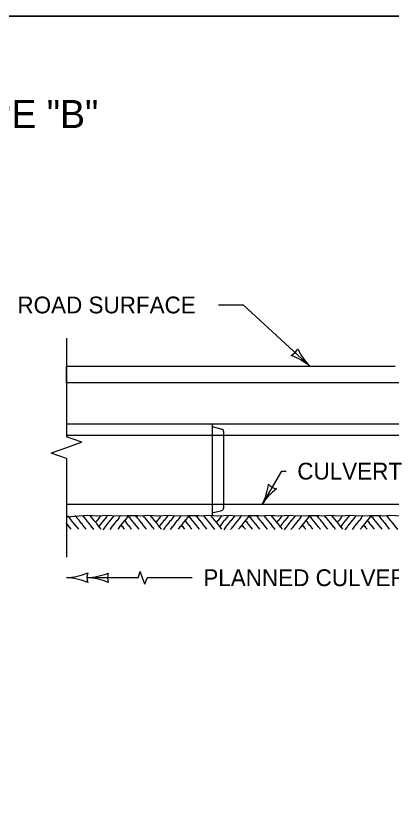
# Model space of a CAD drawing. Extents: x 49991.4 to 50021, y 49987.6 to 50011.4.
# Drawn here: x 50012.469 to 50013.812, y 49996.12 to 49998.999 of the extents above; entities that cross this region are included whole.
import ezdxf

# ---------------------------------------------------------------- set-up
doc = ezdxf.new("R2010")
doc.units = 0
for name, color, linetype in [('Level 1', 7, 'Continuous'), ('Level 2', 7, 'Continuous'), ('Level 3', 7, 'Continuous'), ('Level 4', 7, 'Continuous'), ('Level 6', 7, 'Continuous')]:
    doc.layers.add(name, color=color, linetype=linetype)

msp = doc.modelspace()

# ---------------------------------------------------------------- linework, layer by layer
at = {"layer": 'Level 1'}
for p, q in [((50012.6491, 49997.6892), (50012.6493, 49997.7486)), ((50012.6493, 49997.7486), (50013.8245, 49997.7486)), ((50014.1009, 49997.6892), (50012.6491, 49997.6892)), ((50012.6493, 49997.5423), (50014.7997, 49997.5423)), ((50013.1697, 49997.5423), (50013.1697, 49997.2136))]:
    msp.add_line(p, q, dxfattribs=at)
msp.add_lwpolyline([(49999.3835, 49998.9992), (50016.7501, 49998.9992), (50016.7501, 49987.7988), (49999.3835, 49987.7988)], close=True, dxfattribs=at)
for points in [[(50012.6482, 49997.21), (50012.7245, 49997.2154), (50012.7439, 49997.2142), (50012.7585, 49997.2135)], [(50012.6931, 49997.1653), (50012.6883, 49997.1716), (50012.6867, 49997.1713), (50012.6871, 49997.1727), (50012.6794, 49997.1819), (50012.6799, 49997.1839), (50012.6781, 49997.1841), (50012.6704, 49997.1937), (50012.6687, 49997.1941), (50012.6685, 49997.1959), (50012.6609, 49997.2051), (50012.6613, 49997.207), (50012.6595, 49997.207), (50012.6542, 49997.2135)], [(50012.7195, 49997.1659), (50012.7139, 49997.1731), (50012.7124, 49997.1728), (50012.7127, 49997.1741), (50012.7051, 49997.1835), (50012.7057, 49997.1854), (50012.7037, 49997.1855), (50012.6961, 49997.1953), (50012.6944, 49997.1956), (50012.6943, 49997.1974), (50012.6867, 49997.2065), (50012.6869, 49997.2085), (50012.6849, 49997.2085), (50012.6799, 49997.2149)], [(50012.7473, 49997.1651), (50012.7418, 49997.1725), (50012.7403, 49997.1721), (50012.7405, 49997.1734), (50012.7333, 49997.183), (50012.7335, 49997.1847), (50012.7317, 49997.1849), (50012.7239, 49997.1945), (50012.7223, 49997.195), (50012.7221, 49997.1967), (50012.7147, 49997.2059), (50012.7148, 49997.2076), (50012.7129, 49997.2076), (50012.7079, 49997.2145)], [(50012.7574, 49997.1855), (50012.7502, 49997.1945), (50012.7485, 49997.1951), (50012.7484, 49997.1968), (50012.7407, 49997.2059), (50012.7411, 49997.2079), (50012.7393, 49997.2079), (50012.7337, 49997.2148)], [(50012.7559, 49997.2135), (50012.8029, 49997.2154), (50012.8207, 49997.2133), (50012.8665, 49997.2148), (50012.9049, 49997.2151), (50012.9157, 49997.2136), (50012.9405, 49997.2154), (50012.9597, 49997.2142), (50012.9745, 49997.2135)], [(50012.7723, 49997.2141), (50012.7663, 49997.207), (50012.7669, 49997.2055), (50012.7653, 49997.2055), (50012.7581, 49997.1959), (50012.7573, 49997.1959)], [(50012.7964, 49997.2149), (50012.7904, 49997.2079), (50012.7911, 49997.2065), (50012.7897, 49997.2065), (50012.7823, 49997.1969), (50012.7802, 49997.1969), (50012.7807, 49997.1953), (50012.7729, 49997.1855), (50012.7729, 49997.1839), (50012.7712, 49997.1833), (50012.7651, 49997.1755)], [(50012.8183, 49997.2133), (50012.8127, 49997.2065), (50012.8133, 49997.2052), (50012.8119, 49997.2052), (50012.8047, 49997.1956), (50012.8027, 49997.1956), (50012.8029, 49997.1939), (50012.7952, 49997.1842), (50012.7952, 49997.1825), (50012.7935, 49997.1818), (50012.7862, 49997.1725), (50012.7845, 49997.1722), (50012.7849, 49997.1705), (50012.7795, 49997.1639)], [(50012.8432, 49997.2141), (50012.8371, 49997.207), (50012.8378, 49997.2055), (50012.8365, 49997.2055), (50012.8289, 49997.1959), (50012.8271, 49997.1959), (50012.8273, 49997.1941), (50012.8197, 49997.1847), (50012.8197, 49997.1827), (50012.8179, 49997.1821), (50012.8107, 49997.1727), (50012.8089, 49997.1727), (50012.8093, 49997.1707), (50012.8041, 49997.1644)], [(50012.8717, 49997.2149), (50012.8657, 49997.2076), (50012.8665, 49997.2064), (50012.8649, 49997.2064), (50012.8577, 49997.1968), (50012.8558, 49997.1968), (50012.8559, 49997.1951), (50012.8483, 49997.1855), (50012.8483, 49997.1836), (50012.8467, 49997.1831), (50012.8393, 49997.1737), (50012.8377, 49997.1735), (50012.8379, 49997.1716), (50012.8325, 49997.1653)], [(50012.9091, 49997.1653), (50012.9043, 49997.1716), (50012.9027, 49997.1713), (50012.9029, 49997.1727), (50012.8954, 49997.1819), (50012.8957, 49997.1839), (50012.8941, 49997.1841), (50012.8864, 49997.1937), (50012.8847, 49997.1941), (50012.8845, 49997.1959), (50012.8769, 49997.2051), (50012.8773, 49997.207), (50012.8753, 49997.207), (50012.8702, 49997.2135)], [(50012.9355, 49997.1659), (50012.9299, 49997.1731), (50012.9284, 49997.1728), (50012.9285, 49997.1741), (50012.9211, 49997.1835), (50012.9213, 49997.1854), (50012.9197, 49997.1855), (50012.9121, 49997.1953), (50012.9104, 49997.1956), (50012.9103, 49997.1974), (50012.9027, 49997.2065), (50012.9029, 49997.2085), (50012.9009, 49997.2085), (50012.8959, 49997.2149)], [(50012.9633, 49997.1651), (50012.9578, 49997.1725), (50012.9563, 49997.1721), (50012.9565, 49997.1734), (50012.9489, 49997.183), (50012.9494, 49997.1847), (50012.9477, 49997.1849), (50012.9399, 49997.1945), (50012.9383, 49997.195), (50012.9381, 49997.1967), (50012.9307, 49997.2059), (50012.9308, 49997.2076), (50012.9289, 49997.2076), (50012.9239, 49997.2145)], [(50012.9734, 49997.1855), (50012.9662, 49997.1945), (50012.9644, 49997.1951), (50012.9643, 49997.1968), (50012.9567, 49997.2059), (50012.9569, 49997.2079), (50012.9549, 49997.2079), (50012.9497, 49997.2148)], [(50012.9719, 49997.2135), (50013.0189, 49997.2154), (50013.0367, 49997.2133), (50013.0825, 49997.2148), (50013.1209, 49997.2151), (50013.1313, 49997.2136), (50013.1564, 49997.2154), (50013.1757, 49997.2142), (50013.1905, 49997.2135)], [(50012.9883, 49997.2141), (50012.9823, 49997.207), (50012.9829, 49997.2055), (50012.9813, 49997.2055), (50012.9741, 49997.1959), (50012.9733, 49997.1959)], [(50013.0123, 49997.2149), (50013.0064, 49997.2079), (50013.0069, 49997.2065), (50013.0057, 49997.2065), (50012.9981, 49997.1969), (50012.9962, 49997.1969), (50012.9963, 49997.1953), (50012.9887, 49997.1855), (50012.9887, 49997.1839), (50012.9871, 49997.1833), (50012.9811, 49997.1755)], [(50013.0343, 49997.2133), (50013.0289, 49997.2065), (50013.0293, 49997.2052), (50013.0281, 49997.2052), (50013.0207, 49997.1956), (50013.0187, 49997.1956), (50013.0189, 49997.1939), (50013.0112, 49997.1842), (50013.0112, 49997.1825), (50013.0095, 49997.1818), (50013.0022, 49997.1725), (50013.0004, 49997.1722), (50013.0007, 49997.1705), (50012.9955, 49997.1639)], [(50013.0592, 49997.2141), (50013.0531, 49997.207), (50013.0538, 49997.2055), (50013.0525, 49997.2055), (50013.0449, 49997.1959), (50013.0431, 49997.1959), (50013.0433, 49997.1941), (50013.0357, 49997.1847), (50013.0357, 49997.1827), (50013.0339, 49997.1821), (50013.0267, 49997.1727), (50013.0249, 49997.1727), (50013.0251, 49997.1707), (50013.0199, 49997.1644)], [(50013.0877, 49997.2149), (50013.0817, 49997.2076), (50013.0825, 49997.2064), (50013.0809, 49997.2064), (50013.0737, 49997.1968), (50013.0718, 49997.1968), (50013.0719, 49997.1951), (50013.0643, 49997.1855), (50013.0643, 49997.1836), (50013.0627, 49997.1831), (50013.0553, 49997.1737), (50013.0533, 49997.1735), (50013.0538, 49997.1716), (50013.0485, 49997.1653)], [(50013.1251, 49997.1653), (50013.1203, 49997.1716), (50013.1187, 49997.1713), (50013.1189, 49997.1727), (50013.1114, 49997.1819), (50013.1117, 49997.1839), (50013.1101, 49997.1841), (50013.1024, 49997.1937), (50013.1007, 49997.1941), (50013.1005, 49997.1959), (50013.0928, 49997.2051), (50013.0933, 49997.207), (50013.0913, 49997.207), (50013.0862, 49997.2135)], [(50013.1513, 49997.1659), (50013.1459, 49997.1731), (50013.1444, 49997.1728), (50013.1445, 49997.1741), (50013.1371, 49997.1835), (50013.1373, 49997.1854), (50013.1357, 49997.1855), (50013.1281, 49997.1953), (50013.1264, 49997.1956), (50013.1263, 49997.1974), (50013.1185, 49997.2065), (50013.1189, 49997.2085), (50013.1169, 49997.2085), (50013.1119, 49997.2149)], [(50013.1792, 49997.1651), (50013.1738, 49997.1725), (50013.1721, 49997.1721), (50013.1725, 49997.1734), (50013.1649, 49997.183), (50013.1654, 49997.1847), (50013.1637, 49997.1849), (50013.1559, 49997.1945), (50013.1543, 49997.195), (50013.1541, 49997.1967), (50013.1463, 49997.2059), (50013.1468, 49997.2076), (50013.1449, 49997.2076), (50013.1399, 49997.2145)], [(50013.1893, 49997.1855), (50013.1821, 49997.1945), (50013.1804, 49997.1951), (50013.1803, 49997.1968), (50013.1727, 49997.2059), (50013.1729, 49997.2079), (50013.1709, 49997.2079), (50013.1657, 49997.2148)], [(50013.1879, 49997.2135), (50013.2349, 49997.2154), (50013.2527, 49997.2133), (50013.2983, 49997.2148), (50013.3367, 49997.2151), (50013.3473, 49997.2136), (50013.3724, 49997.2154), (50013.3917, 49997.2142), (50013.4063, 49997.2135)], [(50013.2043, 49997.2141), (50013.1983, 49997.207), (50013.1989, 49997.2055), (50013.1973, 49997.2055), (50013.1899, 49997.1959), (50013.1889, 49997.1959)], [(50013.2283, 49997.2149), (50013.2223, 49997.2079), (50013.2229, 49997.2065), (50013.2217, 49997.2065), (50013.2141, 49997.1969), (50013.2122, 49997.1969), (50013.2123, 49997.1953), (50013.2047, 49997.1855), (50013.2047, 49997.1839), (50013.2031, 49997.1833), (50013.1971, 49997.1755)], [(50013.2503, 49997.2133), (50013.2447, 49997.2065), (50013.2453, 49997.2052), (50013.2439, 49997.2052), (50013.2367, 49997.1956), (50013.2347, 49997.1956), (50013.2349, 49997.1939), (50013.2272, 49997.1842), (50013.2272, 49997.1825), (50013.2255, 49997.1818), (50013.2182, 49997.1725), (50013.2164, 49997.1722), (50013.2167, 49997.1705), (50013.2115, 49997.1639)], [(50013.2751, 49997.2141), (50013.2691, 49997.207), (50013.2698, 49997.2055), (50013.2683, 49997.2055), (50013.2609, 49997.1959), (50013.2591, 49997.1959), (50013.2593, 49997.1941), (50013.2517, 49997.1847), (50013.2517, 49997.1827), (50013.2499, 49997.1821), (50013.2427, 49997.1727), (50013.2407, 49997.1727), (50013.2411, 49997.1707), (50013.2359, 49997.1644)], [(50013.3035, 49997.2149), (50013.2977, 49997.2076), (50013.2985, 49997.2064), (50013.2969, 49997.2064), (50013.2897, 49997.1968), (50013.2877, 49997.1968), (50013.2879, 49997.1951), (50013.2803, 49997.1855), (50013.2803, 49997.1836), (50013.2787, 49997.1831), (50013.2713, 49997.1737), (50013.2693, 49997.1735), (50013.2698, 49997.1716), (50013.2645, 49997.1653)], [(50013.3411, 49997.1653), (50013.3363, 49997.1716), (50013.3345, 49997.1713), (50013.3349, 49997.1727), (50013.3274, 49997.1819), (50013.3277, 49997.1839), (50013.3261, 49997.1841), (50013.3184, 49997.1937), (50013.3167, 49997.1941), (50013.3165, 49997.1959), (50013.3088, 49997.2051), (50013.3093, 49997.207), (50013.3073, 49997.207), (50013.3022, 49997.2135)], [(50013.3675, 49997.1659), (50013.3619, 49997.1731), (50013.3603, 49997.1728), (50013.3605, 49997.1741), (50013.3531, 49997.1835), (50013.3533, 49997.1854), (50013.3517, 49997.1855), (50013.3441, 49997.1953), (50013.3424, 49997.1956), (50013.3423, 49997.1974), (50013.3345, 49997.2065), (50013.3349, 49997.2085), (50013.3329, 49997.2085), (50013.3279, 49997.2149)], [(50013.3952, 49997.1651), (50013.3898, 49997.1725), (50013.3881, 49997.1721), (50013.3885, 49997.1734), (50013.3809, 49997.183), (50013.3814, 49997.1847), (50013.3795, 49997.1849), (50013.3719, 49997.1945), (50013.3703, 49997.195), (50013.3699, 49997.1967), (50013.3623, 49997.2059), (50013.3628, 49997.2076), (50013.3609, 49997.2076), (50013.3559, 49997.2145)], [(50013.4053, 49997.1855), (50013.3981, 49997.1945), (50013.3964, 49997.1951), (50013.3963, 49997.1968), (50013.3887, 49997.2059), (50013.3889, 49997.2079), (50013.3869, 49997.2079), (50013.3817, 49997.2148)], [(50013.4039, 49997.2135), (50013.4509, 49997.2154), (50013.4687, 49997.2133), (50013.5143, 49997.2148), (50013.5527, 49997.2151), (50013.5633, 49997.2136), (50013.5884, 49997.2154), (50013.6077, 49997.2142), (50013.6223, 49997.2135)], [(50013.4203, 49997.2141), (50013.4143, 49997.207), (50013.4149, 49997.2055), (50013.4133, 49997.2055), (50013.4059, 49997.1959), (50013.4049, 49997.1959)], [(50013.4443, 49997.2149), (50013.4384, 49997.2079), (50013.4389, 49997.2065), (50013.4377, 49997.2065), (50013.4301, 49997.1969), (50013.4282, 49997.1969), (50013.4283, 49997.1953), (50013.4207, 49997.1855), (50013.4207, 49997.1839), (50013.4191, 49997.1833), (50013.4131, 49997.1755)], [(50013.4663, 49997.2133), (50013.4607, 49997.2065), (50013.4613, 49997.2052), (50013.4599, 49997.2052), (50013.4523, 49997.1956), (50013.4505, 49997.1956), (50013.4509, 49997.1939), (50013.4432, 49997.1842), (50013.4432, 49997.1825), (50013.4415, 49997.1818), (50013.4342, 49997.1725), (50013.4324, 49997.1722), (50013.4327, 49997.1705), (50013.4275, 49997.1639)], [(50013.4911, 49997.2141), (50013.4851, 49997.207), (50013.4858, 49997.2055), (50013.4843, 49997.2055), (50013.4769, 49997.1959), (50013.4749, 49997.1959), (50013.4753, 49997.1941), (50013.4677, 49997.1847), (50013.4677, 49997.1827), (50013.4659, 49997.1821), (50013.4587, 49997.1727), (50013.4567, 49997.1727), (50013.4571, 49997.1707), (50013.4519, 49997.1644)], [(50013.5195, 49997.2149), (50013.5137, 49997.2076), (50013.5145, 49997.2064), (50013.5129, 49997.2064), (50013.5055, 49997.1968), (50013.5037, 49997.1968), (50013.5038, 49997.1951), (50013.4963, 49997.1855), (50013.4963, 49997.1836), (50013.4943, 49997.1831), (50013.4873, 49997.1737), (50013.4853, 49997.1735), (50013.4858, 49997.1716), (50013.4805, 49997.1653)], [(50013.5569, 49997.1653), (50013.5519, 49997.1716), (50013.5505, 49997.1713), (50013.5509, 49997.1727), (50013.5434, 49997.1819), (50013.5437, 49997.1839), (50013.5419, 49997.1841), (50013.5344, 49997.1937), (50013.5327, 49997.1941), (50013.5325, 49997.1959), (50013.5248, 49997.2051), (50013.5249, 49997.207), (50013.5233, 49997.207), (50013.5182, 49997.2135)], [(50013.5833, 49997.1659), (50013.5777, 49997.1731), (50013.5763, 49997.1728), (50013.5765, 49997.1741), (50013.5691, 49997.1835), (50013.5693, 49997.1854), (50013.5675, 49997.1855), (50013.5601, 49997.1953), (50013.5584, 49997.1956), (50013.5583, 49997.1974), (50013.5505, 49997.2065), (50013.5507, 49997.2085), (50013.5489, 49997.2085), (50013.5437, 49997.2149)], [(50013.6112, 49997.1651), (50013.6057, 49997.1725), (50013.6041, 49997.1721), (50013.6045, 49997.1734), (50013.5969, 49997.183), (50013.5974, 49997.1847), (50013.5955, 49997.1849), (50013.5879, 49997.1945), (50013.5863, 49997.195), (50013.5861, 49997.1967), (50013.5783, 49997.2059), (50013.5788, 49997.2076), (50013.5769, 49997.2076), (50013.5719, 49997.2145)], [(50013.6213, 49997.1855), (50013.6141, 49997.1945), (50013.6124, 49997.1951), (50013.6123, 49997.1968), (50013.6045, 49997.2059), (50013.6049, 49997.2079), (50013.6029, 49997.2079), (50013.5977, 49997.2148)], [(50013.6364, 49997.2141), (50013.6304, 49997.207), (50013.6311, 49997.2055), (50013.6297, 49997.2055), (50013.6221, 49997.1959), (50013.6213, 49997.1959)], [(50013.6233, 49997.2135), (50013.6705, 49997.2154), (50013.6883, 49997.2133), (50013.7339, 49997.2148), (50013.7725, 49997.2151), (50013.7829, 49997.2136), (50013.8079, 49997.2154), (50013.8272, 49997.2142), (50013.8419, 49997.2135)], [(50013.6609, 49997.2149), (50013.6549, 49997.2079), (50013.6557, 49997.2065), (50013.6544, 49997.2065), (50013.6469, 49997.1969), (50013.6449, 49997.1969), (50013.6453, 49997.1953), (50013.6375, 49997.1855), (50013.6375, 49997.1839), (50013.6358, 49997.1833), (50013.6298, 49997.1755)], [(50013.6837, 49997.2133), (50013.6779, 49997.2065), (50013.6787, 49997.2052), (50013.6772, 49997.2052), (50013.6699, 49997.1956), (50013.6679, 49997.1956), (50013.6682, 49997.1939), (50013.6605, 49997.1842), (50013.6605, 49997.1825), (50013.6589, 49997.1818), (50013.6515, 49997.1725), (50013.6497, 49997.1722), (50013.6501, 49997.1705), (50013.6448, 49997.1639)], [(50013.7093, 49997.2141), (50013.7033, 49997.207), (50013.7041, 49997.2055), (50013.7025, 49997.2055), (50013.6951, 49997.1959), (50013.6933, 49997.1959), (50013.6934, 49997.1941), (50013.6857, 49997.1847), (50013.6857, 49997.1827), (50013.6839, 49997.1821), (50013.6769, 49997.1727), (50013.6749, 49997.1727), (50013.6754, 49997.1707), (50013.6701, 49997.1644)], [(50013.7387, 49997.2149), (50013.7329, 49997.2076), (50013.7337, 49997.2064), (50013.7323, 49997.2064), (50013.7247, 49997.1968), (50013.7228, 49997.1968), (50013.7229, 49997.1951), (50013.7153, 49997.1855), (50013.7153, 49997.1836), (50013.7138, 49997.1831), (50013.7063, 49997.1737), (50013.7047, 49997.1735), (50013.7049, 49997.1716), (50013.6997, 49997.1653)], [(50013.7774, 49997.1653), (50013.7725, 49997.1716), (50013.7709, 49997.1713), (50013.7713, 49997.1727), (50013.7637, 49997.1819), (50013.7642, 49997.1839), (50013.7624, 49997.1841), (50013.7547, 49997.1937), (50013.7529, 49997.1941), (50013.7528, 49997.1959), (50013.7451, 49997.2051), (50013.7455, 49997.207), (50013.7437, 49997.207), (50013.7385, 49997.2135)], [(50013.8045, 49997.1659), (50013.7991, 49997.1731), (50013.7973, 49997.1728), (50013.7978, 49997.1741), (50013.7903, 49997.1835), (50013.7907, 49997.1854), (50013.7888, 49997.1855), (50013.7813, 49997.1953), (50013.7797, 49997.1956), (50013.7792, 49997.1974), (50013.7717, 49997.2065), (50013.7721, 49997.2085), (50013.7702, 49997.2085), (50013.7653, 49997.2149)], [(50013.8333, 49997.1651), (50013.8279, 49997.1725), (50013.8263, 49997.1721), (50013.8267, 49997.1734), (50013.8193, 49997.183), (50013.8195, 49997.1847), (50013.8177, 49997.1849), (50013.8103, 49997.1945), (50013.8085, 49997.195), (50013.8081, 49997.1967), (50013.8007, 49997.2059), (50013.8009, 49997.2076), (50013.7991, 49997.2076), (50013.7941, 49997.2145)], [(50012.6661, 49997.1661), (50012.6482, 49997.1885)], [(50012.7573, 49997.1959), (50012.7562, 49997.1959), (50012.7563, 49997.1941), (50012.7537, 49997.1907)], [(50012.7731, 49997.1653), (50012.7677, 49997.1727), (50012.7663, 49997.1722), (50012.7664, 49997.1735), (50012.7591, 49997.183), (50012.7593, 49997.1848), (50012.7575, 49997.1849), (50012.7569, 49997.1855)], [(50012.8569, 49997.1656), (50012.8517, 49997.1722), (50012.8519, 49997.1741), (50012.8499, 49997.1741), (50012.8449, 49997.1809)], [(50012.8821, 49997.1661), (50012.8733, 49997.1771), (50012.8717, 49997.1775), (50012.8715, 49997.1791), (50012.8641, 49997.1884), (50012.8642, 49997.1902), (50012.8624, 49997.1902), (50012.8575, 49997.1968)], [(50012.9733, 49997.1959), (50012.9722, 49997.1959), (50012.9723, 49997.1941), (50012.9697, 49997.1907)], [(50012.9891, 49997.1653), (50012.9837, 49997.1727), (50012.9823, 49997.1722), (50012.9825, 49997.1735), (50012.9749, 49997.183), (50012.9753, 49997.1848), (50012.9735, 49997.1849), (50012.9733, 49997.1855)], [(50013.0729, 49997.1656), (50013.0677, 49997.1722), (50013.0679, 49997.1741), (50013.0659, 49997.1741), (50013.0609, 49997.1809)], [(50013.0981, 49997.1661), (50013.0893, 49997.1771), (50013.0877, 49997.1775), (50013.0875, 49997.1791), (50013.0801, 49997.1884), (50013.0802, 49997.1902), (50013.0784, 49997.1902), (50013.0733, 49997.1968)], [(50013.1893, 49997.1959), (50013.1882, 49997.1959), (50013.1883, 49997.1941), (50013.1857, 49997.1907)], [(50013.2051, 49997.1653), (50013.1997, 49997.1727), (50013.1983, 49997.1722), (50013.1984, 49997.1735), (50013.1909, 49997.183), (50013.1912, 49997.1848), (50013.1895, 49997.1849), (50013.1889, 49997.1855)], [(50013.2889, 49997.1656), (50013.2835, 49997.1722), (50013.2839, 49997.1741), (50013.2819, 49997.1741), (50013.2767, 49997.1809)], [(50013.3141, 49997.1661), (50013.3053, 49997.1771), (50013.3037, 49997.1775), (50013.3035, 49997.1791), (50013.2959, 49997.1884), (50013.2962, 49997.1902), (50013.2944, 49997.1902), (50013.2893, 49997.1968)], [(50013.4049, 49997.1959), (50013.4042, 49997.1959), (50013.4043, 49997.1941), (50013.4017, 49997.1907)], [(50013.4211, 49997.1653), (50013.4157, 49997.1727), (50013.4139, 49997.1722), (50013.4144, 49997.1735), (50013.4069, 49997.183), (50013.4072, 49997.1848), (50013.4055, 49997.1849), (50013.4049, 49997.1855)], [(50013.5049, 49997.1656), (50013.4995, 49997.1722), (50013.4999, 49997.1741), (50013.4979, 49997.1741), (50013.4927, 49997.1809)], [(50013.5301, 49997.1661), (50013.5213, 49997.1771), (50013.5197, 49997.1775), (50013.5194, 49997.1791), (50013.5119, 49997.1884), (50013.5121, 49997.1902), (50013.5104, 49997.1902), (50013.5053, 49997.1968)], [(50013.6209, 49997.1959), (50013.6201, 49997.1959), (50013.6203, 49997.1941), (50013.6173, 49997.1907)], [(50013.6373, 49997.1653), (50013.6319, 49997.1727), (50013.6304, 49997.1722), (50013.6305, 49997.1735), (50013.6231, 49997.183), (50013.6233, 49997.1848), (50013.6217, 49997.1849), (50013.6213, 49997.1855)], [(50013.7241, 49997.1656), (50013.7187, 49997.1722), (50013.7189, 49997.1741), (50013.7169, 49997.1741), (50013.7119, 49997.1809)], [(50013.7498, 49997.1661), (50013.7413, 49997.1771), (50013.7395, 49997.1775), (50013.7391, 49997.1791), (50013.7317, 49997.1884), (50013.7319, 49997.1902), (50013.7301, 49997.1902), (50013.7251, 49997.1968)]]:
    msp.add_lwpolyline(points, dxfattribs=at)
at = {"layer": 'Level 2'}
msp.add_line((50016.7501, 49998.9992), (49999.3835, 49998.9992), dxfattribs=at)
at = {"layer": 'Level 3'}
for p, q in [((50013.1924, 49997.9669), (50013.2804, 49997.9669)), ((50013.2804, 49997.9669), (50013.5205, 49997.747)), ((50013.4176, 49997.3731), (50013.3492, 49997.2547)), ((50013.4176, 49997.3731), (50013.4344, 49997.3731)), ((50012.9052, 49996.9922), (50012.9133, 49997.015)), ((50012.9214, 49996.9922), (50012.9133, 49997.015)), ((50012.9052, 49996.9922), (50012.7227, 49996.9922)), ((50012.9295, 49996.9694), (50012.9214, 49996.9922)), ((50012.9295, 49996.9694), (50012.9376, 49996.9922)), ((50013.0986, 49996.9922), (50012.9376, 49996.9922))]:
    msp.add_line(p, q, dxfattribs=at)
for centre, radius, start, end in [((50013.4259, 49997.8336), 0.0548, 299.6524, 335.3747), ((50013.3718, 49997.5676), 0.233, 50.3409, 69.5907), ((50013.6773, 49997.9046), 0.2223, 204.9696, 225.1531), ((50013.1502, 49997.3569), 0.2237, 332.8229, 352.0727), ((50013.4108, 49997.3613), 0.0526, 222.1344, 257.8568), ((50013.5295, 49997.1404), 0.2134, 127.4516, 147.6351), ((50012.6378, 49997.2252), 0.233, 272.8273, 292.0772), ((50012.7775, 49996.9925), 0.0548, 162.1388, 197.8612), ((50012.7112, 49997.2249), 0.233, 272.8273, 292.0772), ((50012.8509, 49996.9922), 0.0548, 162.1388, 197.8612), ((50012.6401, 49996.7703), 0.2223, 67.456, 87.6395), ((50012.7136, 49996.7701), 0.2223, 67.456, 87.6395)]:
    msp.add_arc(centre, radius, start, end, dxfattribs=at)
at = {"layer": 'Level 4'}
for p, q in [((50013.1697, 49997.5321), (50013.2045, 49997.5233)), ((50012.6493, 49997.5013), (50014.8057, 49997.5013)), ((50013.2107, 49997.5152), (50013.2107, 49997.2408)), ((50012.6493, 49997.2547), (50015.1696, 49997.2547)), ((50013.1697, 49997.224), (50013.2046, 49997.2327))]:
    msp.add_line(p, q, dxfattribs=at)
for centre, start, end in [((50013.2025, 49997.5153), 0, 75.8893), ((50013.2025, 49997.2407), 284.1107, 0)]:
    msp.add_arc(centre, 0.00822, start, end, dxfattribs=at)
at = {"layer": 'Level 6'}
for p, q in [((50012.6491, 49997.8486), (50012.6491, 49997.4957)), ((50012.7039, 49997.4762), (50012.6491, 49997.4957)), ((50012.7039, 49997.4762), (50012.6491, 49997.4568)), ((50012.6491, 49997.4568), (50012.5943, 49997.4374)), ((50012.6491, 49997.4179), (50012.5943, 49997.4374)), ((50012.6491, 49997.4179), (50012.6491, 49997.0651))]:
    msp.add_line(p, q, dxfattribs=at)

# ---------------------------------------------------------------- texts
at = {"layer": 'Level 2'}
for s, height, p in [('TYPE "B"', 0.1, (50012.1927, 49998.5992)), ('ROAD SURFACE', 0.06, (50012.4741, 49997.9369)), ('CULVERT', 0.06, (50013.4744, 49997.3431)), ('PLANNED CULVERT LENGTH', 0.06, (50013.1386, 49996.9622))]:
    msp.add_text(s, height=height, dxfattribs=at).set_placement(p)

doc.saveas('drawing.dxf')
